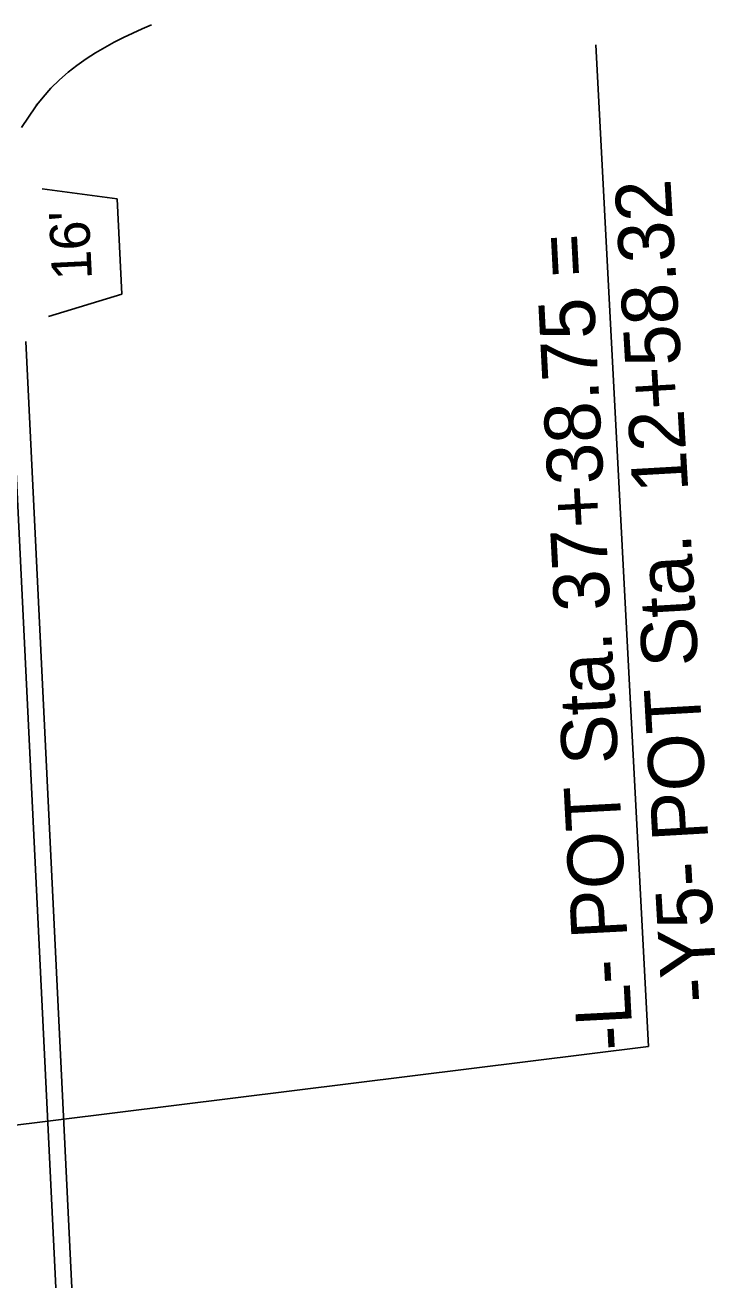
# Model space of a CAD drawing. Extents: x 2367848 to 2369479, y 800728 to 808616.
# Drawn here: x 2368837.9 to 2368924.3, y 804048.8 to 804206 of the extents above; entities that cross this region are included whole.
import ezdxf

# ---------------------------------------------------------------- set-up
doc = ezdxf.new("R2010")
doc.units = 0
for name, color, linetype in [('Prop AutoTurn Projected Path', 7, 'Continuous'), ('Prop AutoTurn Simulation', 7, 'Continuous'), ('Prop Conc 2ft 6in Curb and Gutter', 7, 'Continuous'), ('Prop Dimension', 7, 'Continuous'), ('Prop EOT', 7, 'Continuous'), ('Prop Horizontal Alignment Station Label', 7, 'Continuous')]:
    doc.layers.add(name, color=color, linetype=linetype)

msp = doc.modelspace()

# ---------------------------------------------------------------- linework, layer by layer
at = {"layer": 'Prop AutoTurn Projected Path'}
msp.add_arc((2368857.97, 804186.77), 30, 93.7959, 182.7965, dxfattribs=at)
at = {"layer": 'Prop AutoTurn Simulation'}
for points in [[(2368839.35, 804196), (2368840.12, 804196.95), (2368841.12, 804198.07), (2368842.17, 804199.11), (2368843.26, 804200.07), (2368844.38, 804200.94), (2368845.53, 804201.75), (2368846.69, 804202.5), (2368847.86, 804203.19), (2368849.03, 804203.84), (2368850.21, 804204.43), (2368851.38, 804204.99), (2368852.55, 804205.51), (2368853.72, 804206)], [(2368837.44, 804193.14), (2368839.17, 804195.76), (2368839.35, 804196)]]:
    msp.add_lwpolyline(points, dxfattribs=at)
msp.add_circle((2368839.35, 804196), 0.0417, dxfattribs=at)
msp.add_circle((2368839.35, 804196), 0.0417, dxfattribs=at)
at = {"layer": 'Prop Conc 2ft 6in Curb and Gutter'}
msp.add_line((2368848.66, 803946.97), (2368837.95, 804166.35), dxfattribs=at)
at = {"layer": 'Prop EOT'}
for p, q in [((2368856.01, 803755.6), (2368830.84, 804270.86)), ((2368849.41, 804184.2), (2368840.01, 804185.47)), ((2368849.99, 804172.26), (2368849.41, 804184.2)), ((2368840.8, 804169.49), (2368849.99, 804172.26))]:
    msp.add_line(p, q, dxfattribs=at)
at = {"layer": 'Prop Horizontal Alignment Station Label'}
for p, q in [((2368916.01, 804078.02), (2368909.43, 804203.53)), ((2368822.8, 804066.43), (2368916.01, 804078.02))]:
    msp.add_line(p, q, dxfattribs=at)

# ---------------------------------------------------------------- texts
at = {"layer": 'Prop Dimension'}
msp.add_text("16'", height=5, rotation=92.7965, dxfattribs=at).set_placement((2368846.27, 804174.16))
at = {"layer": 'Prop Horizontal Alignment Station Label'}
for s, rotation, p in [('-Y5- POT Sta.  12+58.32', 93.2805, (2368924.68, 804083.7)), ('-L- POT Sta. 37+38.75 =', 92.9979, (2368914.11, 804077.66))]:
    msp.add_text(s, height=7, rotation=rotation, dxfattribs=at).set_placement(p)

doc.saveas('drawing.dxf')
